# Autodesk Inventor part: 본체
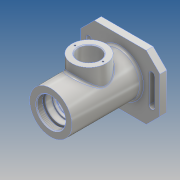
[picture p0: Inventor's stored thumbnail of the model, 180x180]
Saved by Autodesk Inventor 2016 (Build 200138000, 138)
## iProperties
Created: 2017-10
Part Number: 본체
Material: 알루미늄 6061
Document SubType Name: Modeling
Designer: Administrator
Density: 2.7 g/cm^3
Appearance: 알루미늄 - 평지
Mass: 503.258 g
Surface Area: 455.289 cm^2
Volume: 186.392 cm^3
Author: Administrator
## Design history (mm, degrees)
sketch "스케치1"
  geometry: L1 (0, 0)-(115, 0); L2 (0, 0)-(0, 31); L3 (0, 31)-(115, 31); L4 (115, 31)-(115, 0); L5 (0, 21)-(9, 21); L6 (9, 21)-(9, 24); L7 (9, 24)-(12, 24); L8 (12, 24)-(12, 20); L9 (12, 20)-(21, 20); L10 (21, 20)-(21, 17.5); L11 (21, 17.5)-(24.25, 17.5); L12 (24.25, 17.5)-(24.25, 18.5); L13 (24.25, 18.5)-(26, 18.5); L14 (26, 18.5)-(26, 17.5); L15 (26, 17.5)-(37, 17.5); L16 (37, 17.5)-(37, 26); L17 (37, 26)-(75, 26); L18 (75, 26)-(75, 17.5); L19 (75, 17.5)-(85.7, 17.5); L20 (91, 10)-(93.7, 10); L21 (93.7, 10)-(93.7, 12.2); L22 (94, 12.5)-(100.3, 12.5); L23 (86, 17.2)-(86, 16.5); L24 (86, 16.5)-(91, 16.5); L25 (91, 16.5)-(91, 10); L26 (101, 12.904)-(101, 14.022); L27 (102.818, 16.779)-(115, 22); L28 (100.3, 12.5)-(101, 12.904); A1 r 0.3 centre (94, 12.2) between (94, 12.5) and (93.7, 12.2); A2 r 0.3 centre (85.7, 17.2) between (86, 17.2) and (85.7, 17.5); A3 r 3 centre (104, 14.022) between (102.818, 16.779) and (101, 14.022); 4 further points
  constraints: 56 end point, 19 perpendicular, 12 point on line, 6 point on circle, 6 tangent, 3 centre point, 3 vertical, 2 horizontal
  dimensions: "d1" = 115 distance of L2.end L3.end; "d2" = 62 diameter of L3 L1; "d3" = 42 diameter of L5 L1; "d4" = 48 diameter of L7 L1; "d5" = 40 diameter of L9 L1; "d6" = 35 diameter of L11 L1; "d7" = 37 diameter of L13 L1; "d8" = 52 diameter of L17 L1; "d9" = 35 diameter of L19 L1; "d10" = 33 diameter of L24 L1; "d11" = 20 diameter of L20 L1; "d12" = 25 diameter of L22 L1; "d13" = 32 diameter of point (101, 16) L1; "d14" = 44 diameter of L27.end L1; "d15" = 3 distance of L6.end L7.end; "d16" = 12 distance between parallel lines of L2 L8; "d17" = 21 distance between parallel lines of L2 L10; "d18" = 38 distance of L16.end L17.end; "d19" = 14 distance between parallel lines of L4 L26; "d20" = 7.3 distance between parallel lines of L26 L21; "d21" = 2.7 distance of L20.start L20.end; "d22" = 5 distance between parallel lines of L23 L25; "d23" = 26 distance between parallel lines of L2 L14; "d24" = 1.75 distance of L12.end L13.end; "d25" = 11 distance of L18.end point (86, 17.5); "d67" = 0.3 radius of A1; "d68" = 0.7 distance of L22.end point (101, 12.5); "d69" = 30 deg angle of L22 L28; "d70" = 0.3 radius of A2; "d74" = 3 radius of A3
revolve "회전1" sketch "스케치1" stored, may be unused: angle "d26" = 90 deg
node "작업 평면1"
sketch "스케치2"
  geometry: L1 (38, -47)-(-38, -47); L2 (-58, -27)-(-58, 27); L3 (-38, 47)-(38, 47); L4 (58, 27)-(58, -27); L5 (38, 47)-(58, 27); L6 (-58, 27)-(-38, 47); L7 (-58, -27)-(-38, -47); L8 (38, -47)-(58, -27); L9 (42, -20)-(42, 20); L10 (50, 20)-(50, -20); L11 (0, -4.964)-(0, 10.106); L12 (-42, -20)-(-42, 20); L13 (-50, 20)-(-50, -20); C1 r 31 at (0, 0) reference; A1 r 4 centre (46, -20) between (42, -20) and (50, -20); A2 r 4 centre (46, 20) between (42, 20) and (50, 20); A3 r 4 centre (-46, -20) between (-42, -20) and (-50, -20); A4 r 4 centre (-46, 20) between (-42, 20) and (-50, 20); 11 further points
  constraints: 26 end point, 8 point on circle, 8 point on line, 8 symmetric about line, 5 horizontal alignment, 4 centre point, 4 midpoint, 2 parallel, 2 vertical, 2 vertical alignment, 1 horizontal, 1 perpendicular, 1 tangent, 2 other
  dimensions: "d28" = 116 distance between parallel lines of L4 L2; "d29" = 94 distance between parallel lines of L3 L1; "d30" = 20 distance of L3.end point (58, 47); "d31" = 20 distance of L4.start point (58, 47) (= d30); "d32" = 20 distance of L2.end point (-58, 47) (= d30); "d33" = 20 distance of L3.start point (-58, 47) (= d32); "d34" = 20 distance of L2.start point (-58, -47) (= d30); "d35" = 20 distance of L1.end point (-58, -47) (= d34); "d36" = 20 distance of L1.start point (58, -47); "d37" = 20 distance of L4.end point (58, -47) (= d36); "d38" = 8 diameter of A1; "d39" = 8 diameter of A2; "d40" = 40 distance of L10.start L10.end; "d41" = 46 horizontal distance of point (0, 0) A2.centre; "d42" = 46 horizontal distance of point (0, 0) A4.centre
extrude "돌출1" join sketch "스케치2" distance "d43" = 10; taper "d44" = 0 deg
sketch "스케치3"
  geometry: C1 r 31 at (0, 0) reference; C2 r 35 at (0, 0); C3 r 31 at (0, 0) reference
  constraints: 1 centre point, 1 coincident
  dimensions: "d45" = 70 diameter of C2
extrude "돌출2" join sketch "스케치3" distance "d46" = 3; taper "d47" = 0 deg
node "작업 평면2"
sketch "스케치4"
  geometry: C1 r 25 at (0, 56); 1 further point
  constraints: 1 centre point, 1 vertical alignment
  dimensions: "d49" = 50 diameter of C1; "d50" = 56 distance of point (0, 0) C1.centre
extrude "돌출3" join sketch "스케치4" stored distance "d51" = 3; taper "d52" = 0 deg
sketch "스케치5"
  geometry: C1 r 25 at (0, 0) reference; C2 r 16 at (0, 0); 1 further point
  constraints: 1 centre point, 1 coincident
  dimensions: "d53" = 32 diameter of C2
extrude "돌출4" cut sketch "스케치5" stored distance "d54" = 3; taper "d55" = 0 deg
sketch "스케치6"
  geometry: C1 r 16 at (0, 0) reference; 3 further points
  constraints: 2 horizontal alignment
  dimensions: "d56" = 20.5 distance of C1.centre point (-20.5, 0); "d57" = 41 distance of point (20.5, 0) point (-20.5, 0)
hole "구멍1" sketch "스케치6" at (-20.5, 0), (20.5, 0) diameter "d58" = 2.459; stored, may be unused: countersink angle "d62" = 90 deg, drill point angle "d64" = 118 deg; dims "d59" = 6, "d60" = 4, "d61" = 2, "d63" = 8
feature "스레드1" dims "d65" = 10, "d66" = 0
fillet "모깎기1" dims "d71" = 3
fillet "모깎기2" dims "d72" = 3
fillet "모깎기3" dims "d73" = 3
chamfer "모따기1" distance "d75" = 1; stored, may be unused: second distance "d76" = 2, angle "d77" = 45 deg
chamfer "모따기2" distance "d78" = 1; stored, may be unused: second distance "d79" = 2, angle "d80" = 45 deg
node "솔리드1"
other parameters: "d27" = -3, "d48" = 47
